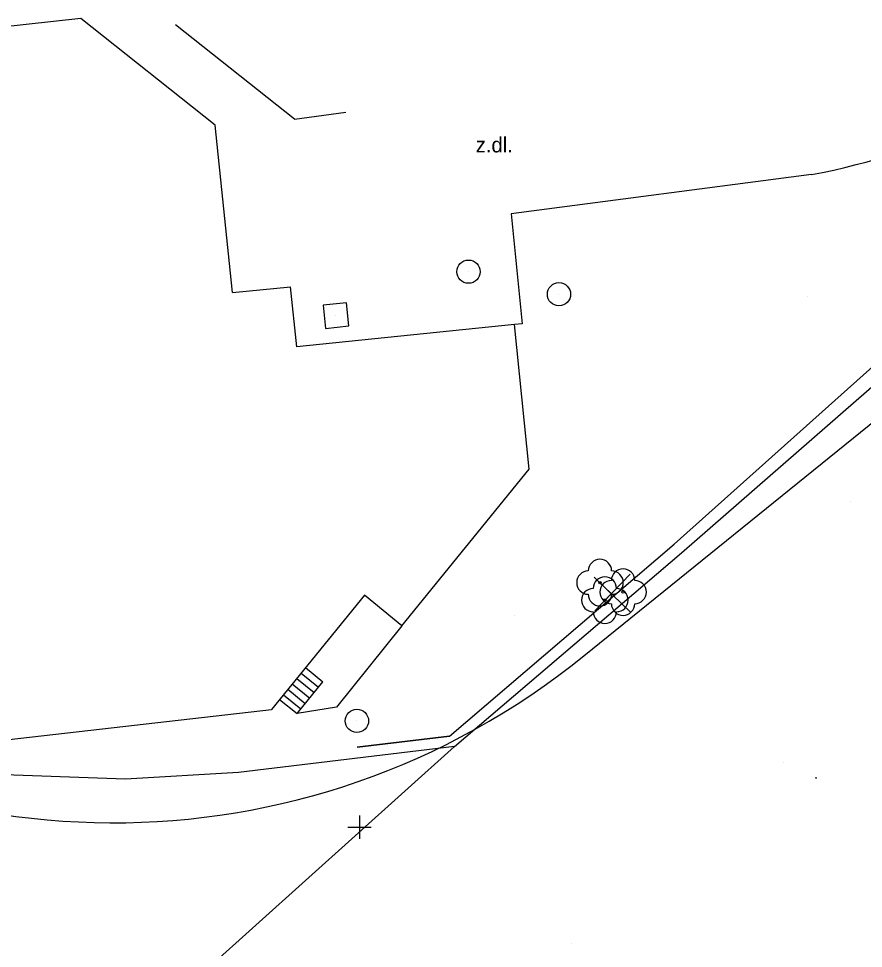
# Model space of a CAD drawing. Extents: x -438200 to -437954, y -1133133 to -1132850.
# Drawn here: x -438114.64 to -438078.37, y -1132955.2 to -1132915.29 of the extents above; entities that cross this region are included whole.
import ezdxf

# ---------------------------------------------------------------- set-up
doc = ezdxf.new("R2010")
doc.units = 0
for name, color, linetype in [('Vrstva 1', 7, 'Continuous'), ('Vrstva 10', 7, 'Continuous'), ('Vrstva 11', 7, 'Continuous'), ('Vrstva 22', 7, 'Continuous'), ('Vrstva 26', 7, 'Continuous'), ('Vrstva 27', 7, 'Continuous'), ('Vrstva 40', 7, 'Continuous'), ('Vrstva 5', 7, 'Continuous'), ('Vrstva 61', 7, 'Continuous'), ('Vrstva 9', 7, 'Continuous')]:
    doc.layers.add(name, color=color, linetype=linetype)

msp = doc.modelspace()

# ---------------------------------------------------------------- linework, layer by layer
at = {"layer": 'Vrstva 1'}
for p, q in [((-438111.968, -1132915.287), (-438111.968, -1132915.287)), ((-438102.793, -1132919.6), (-438102.793, -1132919.6)), ((-438106.192, -1132919.855), (-438106.192, -1132919.855)), ((-438081.733, -1132922.085), (-438081.733, -1132922.085)), ((-438080.604, -1132921.986), (-438080.604, -1132921.986)), ((-438093.499, -1132923.668), (-438093.499, -1132923.668)), ((-438095.324, -1132926.15), (-438095.324, -1132926.15)), ((-438102.958, -1132926.794), (-438102.958, -1132926.794)), ((-438091.439, -1132927.119), (-438091.439, -1132927.119)), ((-438080.777, -1132927.205), (-438080.777, -1132927.205)), ((-438101.013, -1132928.035), (-438101.013, -1132928.035)), ((-438093.353, -1132928.422), (-438093.353, -1132928.422)), ((-438093.344, -1132928.427), (-438093.344, -1132928.427)), ((-438090.373, -1132942.634), (-438074.748, -1132930.004)), ((-438090.373, -1132942.634), (-438074.748, -1132930.004)), ((-438092.714, -1132934.632), (-438092.714, -1132934.632)), ((-438078.935, -1132936.023), (-438078.935, -1132936.023)), ((-438086.179, -1132938.215), (-438086.179, -1132938.215)), ((-438093.352, -1132940.901), (-438093.352, -1132940.901)), ((-438098.181, -1132941.346), (-438098.181, -1132941.346)), ((-438101.588, -1132943.74), (-438101.588, -1132943.74)), ((-438093.309, -1132943.665), (-438093.309, -1132943.665)), ((-438100.997, -1132944.845), (-438100.997, -1132944.845)), ((-438103.779, -1132944.937), (-438103.779, -1132944.937)), ((-438102.682, -1132945.121), (-438102.682, -1132945.121)), ((-438100.113, -1132945.432), (-438100.113, -1132945.432)), ((-438100.102, -1132946.562), (-438100.102, -1132946.562)), ((-438095.924, -1132946.534), (-438095.924, -1132946.534)), ((-438081.785, -1132947.234), (-438081.785, -1132947.234)), ((-438105.196, -1132947.647), (-438105.196, -1132947.647)), ((-438110.044, -1132947.938), (-438110.044, -1132947.938)), ((-438105.18, -1132954.94), (-438105.18, -1132954.94)), ((-438090.905, -1132955.008), (-438090.905, -1132955.008))]:
    msp.add_line(p, q, dxfattribs=at)
msp.add_circle((-438080.404, -1132947.882), 0.0127, dxfattribs=at)
msp.add_circle((-438080.404, -1132947.882), 0.0127, dxfattribs=at)
msp.add_arc((-438110.563, -1132917.807), 32, 230.3365, 309.1186, dxfattribs=at)
msp.add_arc((-438110.563, -1132917.807), 32, 230.3365, 309.1186, dxfattribs=at)
at = {"layer": 'Vrstva 10'}
msp.add_line((-438095.924, -1132946.534), (-438114.084, -1132962.853), dxfattribs=at)
for points in [[(-438095.924, -1132946.534), (-438086.179, -1132938.215), (-438074.983, -1132928.454)], [(-438095.924, -1132946.534), (-438105.196, -1132947.647), (-438110.044, -1132947.938), (-438116.055, -1132947.713), (-438119.29, -1132946.982), (-438123.021, -1132946.022)]]:
    msp.add_lwpolyline(points, dxfattribs=at)
at = {"layer": 'Vrstva 11'}
for p, q in [((-438102.319, -1132943.145), (-438101.57, -1132943.755)), ((-438102.698, -1132943.61), (-438101.949, -1132944.22)), ((-438102.508, -1132943.378), (-438101.759, -1132943.988)), ((-438102.887, -1132943.843), (-438102.138, -1132944.453)), ((-438103.266, -1132944.308), (-438102.517, -1132944.918)), ((-438103.077, -1132944.075), (-438102.328, -1132944.685)), ((-438103.431, -1132944.511), (-438102.682, -1132945.121))]:
    msp.add_line(p, q, dxfattribs=at)
for points in [[(-438102.793, -1132919.6), (-438107.901, -1132915.561)], [(-438102.793, -1132919.6), (-438100.584, -1132919.31)], [(-438080.604, -1132921.986), (-438093.499, -1132923.668), (-438093.013, -1132928.387), (-438093.353, -1132928.422)], [(-438098.181, -1132941.346), (-438100.997, -1132944.845), (-438102.682, -1132945.121)], [(-438102.682, -1132945.121), (-438101.57, -1132943.755)]]:
    msp.add_lwpolyline(points, dxfattribs=at)
msp.add_arc((-438086.316, -1132891.925), 30.599, 280.7582, 295.4891, dxfattribs=at)
at = {"layer": 'Vrstva 22'}
for centre in [(-438089.68, -1132939.498), (-438088.688, -1132939.904), (-438089.469, -1132940.248)]:
    msp.add_circle(centre, 0.05, dxfattribs=at)
for centre, start, end in [((-438089.68, -1132938.998), 0, 180), ((-438090.18, -1132939.498), 90, 270), ((-438089.469, -1132939.748), 0, 180), ((-438088.688, -1132939.404), 0, 180), ((-438089.18, -1132939.498), 270, 90), ((-438089.188, -1132939.904), 90, 270), ((-438088.188, -1132939.904), 270, 90), ((-438089.969, -1132940.248), 90, 270), ((-438089.68, -1132939.998), 180, 0), ((-438088.969, -1132940.248), 270, 90), ((-438088.688, -1132940.404), 180, 0), ((-438089.469, -1132940.748), 180, 0)]:
    msp.add_arc(centre, 0.5, start, end, dxfattribs=at)
at = {"layer": 'Vrstva 26'}
msp.add_lwpolyline([(-438100.567, -1132927.486), (-438101.562, -1132927.589), (-438101.459, -1132928.584), (-438100.464, -1132928.481)], close=True, dxfattribs=at)
at = {"layer": 'Vrstva 27'}
for centre in [(-438095.324, -1132926.15), (-438091.439, -1132927.119), (-438100.113, -1132945.432)]:
    msp.add_circle(centre, 0.5, dxfattribs=at)
at = {"layer": 'Vrstva 40'}
msp.add_lwpolyline([(-438088.386, -1132939.139), (-438089.906, -1132940.705), (-438089.195, -1132939.972), (-438089.928, -1132939.261), (-438088.356, -1132940.787)], dxfattribs=at)
at = {"layer": 'Vrstva 5'}
for p, q in [((-438105.451, -1132927.051), (-438106.192, -1132919.855)), ((-438105.451, -1132927.051), (-438102.958, -1132926.794)), ((-438102.691, -1132929.383), (-438102.958, -1132926.794)), ((-438093.353, -1132928.422), (-438102.691, -1132929.383)), ((-438092.714, -1132934.632), (-438093.353, -1132928.422)), ((-438098.181, -1132941.346), (-438092.714, -1132934.632)), ((-438099.789, -1132940.037), (-438103.778, -1132944.938)), ((-438098.181, -1132941.346), (-438099.789, -1132940.037)), ((-438115.881, -1132946.325), (-438103.779, -1132944.937))]:
    msp.add_line(p, q, dxfattribs=at)
for points in [[(-438111.968, -1132915.287), (-438125.93, -1132916.81), (-438130.7, -1132922.46)], [(-438106.192, -1132919.855), (-438111.968, -1132915.287)]]:
    msp.add_lwpolyline(points, dxfattribs=at)
at = {"layer": 'Vrstva 61'}
for p, q in [((-438100, -1132949.5), (-438100, -1132950.5)), ((-438100.5, -1132950), (-438099.5, -1132950))]:
    msp.add_line(p, q, dxfattribs=at)
at = {"layer": 'Vrstva 9'}
for points in [[(-438100.102, -1132946.562), (-438096.145, -1132946.087), (-438086.495, -1132937.848), (-438075.407, -1132927.936)], [(-438096.145, -1132946.087), (-438100.102, -1132946.562)]]:
    msp.add_lwpolyline(points, dxfattribs=at)

# ---------------------------------------------------------------- texts
at = {"layer": 'Vrstva 40'}
msp.add_text('z.dl.', height=0.65, dxfattribs=at).set_placement((-438095.015, -1132921.031))

doc.saveas('drawing.dxf')
